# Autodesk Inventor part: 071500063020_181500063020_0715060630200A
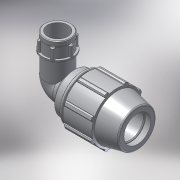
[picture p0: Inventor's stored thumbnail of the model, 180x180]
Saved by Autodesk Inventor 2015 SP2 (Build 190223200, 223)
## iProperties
Created: 2017-02
Part Number: 071500063020_181500063020_0715060630200A
Material: PVC-Piping
Description: PLASSON 90° ELBOW FEMALE ADAPTOR 63-2"
Document SubType Name: Modeling
Designer: KIM
Mass: 92.6774 g
Surface Area: 199.44 cm^2
Volume: 66.1981 cm^3
Density: 1.4 g/cm^3
Appearance: Smooth - White
Author: KIM
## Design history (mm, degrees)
derived "07150.ipt"
feature "Solid1::07150.ipt"
tag "TaggingFeature1"
body "Solid1"
other parameters: "d2" = 63, "d4" = 13.33333, "d7" = 113, "d9" = 22.85714, "d11" = 5.33333, "d13" = 120 deg, "d14" = 81.9, "d15" = 12 deg, "d16" = 98.31, "d18" = 3.15, "d19" = 35 deg, "d20" = 17.5 deg, "d21" = 105.09, "d23" = 0, "d25" = 360 deg, "d27" = 2.26, "d33" = 1.26, "d42" = 59.2, "d43" = 3.39, "d46" = 1.89, "d68" = 5.33333, "d73" = 73.6528, "d75" = 84.70072, "d76" = 56.656, "d77" = 33, "d79" = 22.6624, "d80" = 1.69968, "d83" = 0, "d84" = 0, "d91" = 84.75, "d94" = 56.656, "d95" = 39.6592, "d96" = 13.33333, "d97" = 50 deg, "d98" = 50.9904, "d99" = 0.5, "d100" = 0.5, "d101" = 10, "d102" = 73.6528, "d103" = 25.5, "d104" = 0, "d108" = 360 deg, "d110" = 2.20958, "d_" = 63, "E_" = 113, "Rp_" = 56.656, "d105" = 11.04792
